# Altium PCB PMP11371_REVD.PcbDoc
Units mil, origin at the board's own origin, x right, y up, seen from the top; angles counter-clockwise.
Board outline 3400 x 2100 mil, 2 copper layers (Top Layer, Bottom Layer), stack 62 mil thick; 63 components, 36 nets, 176 pads, 55 vias.
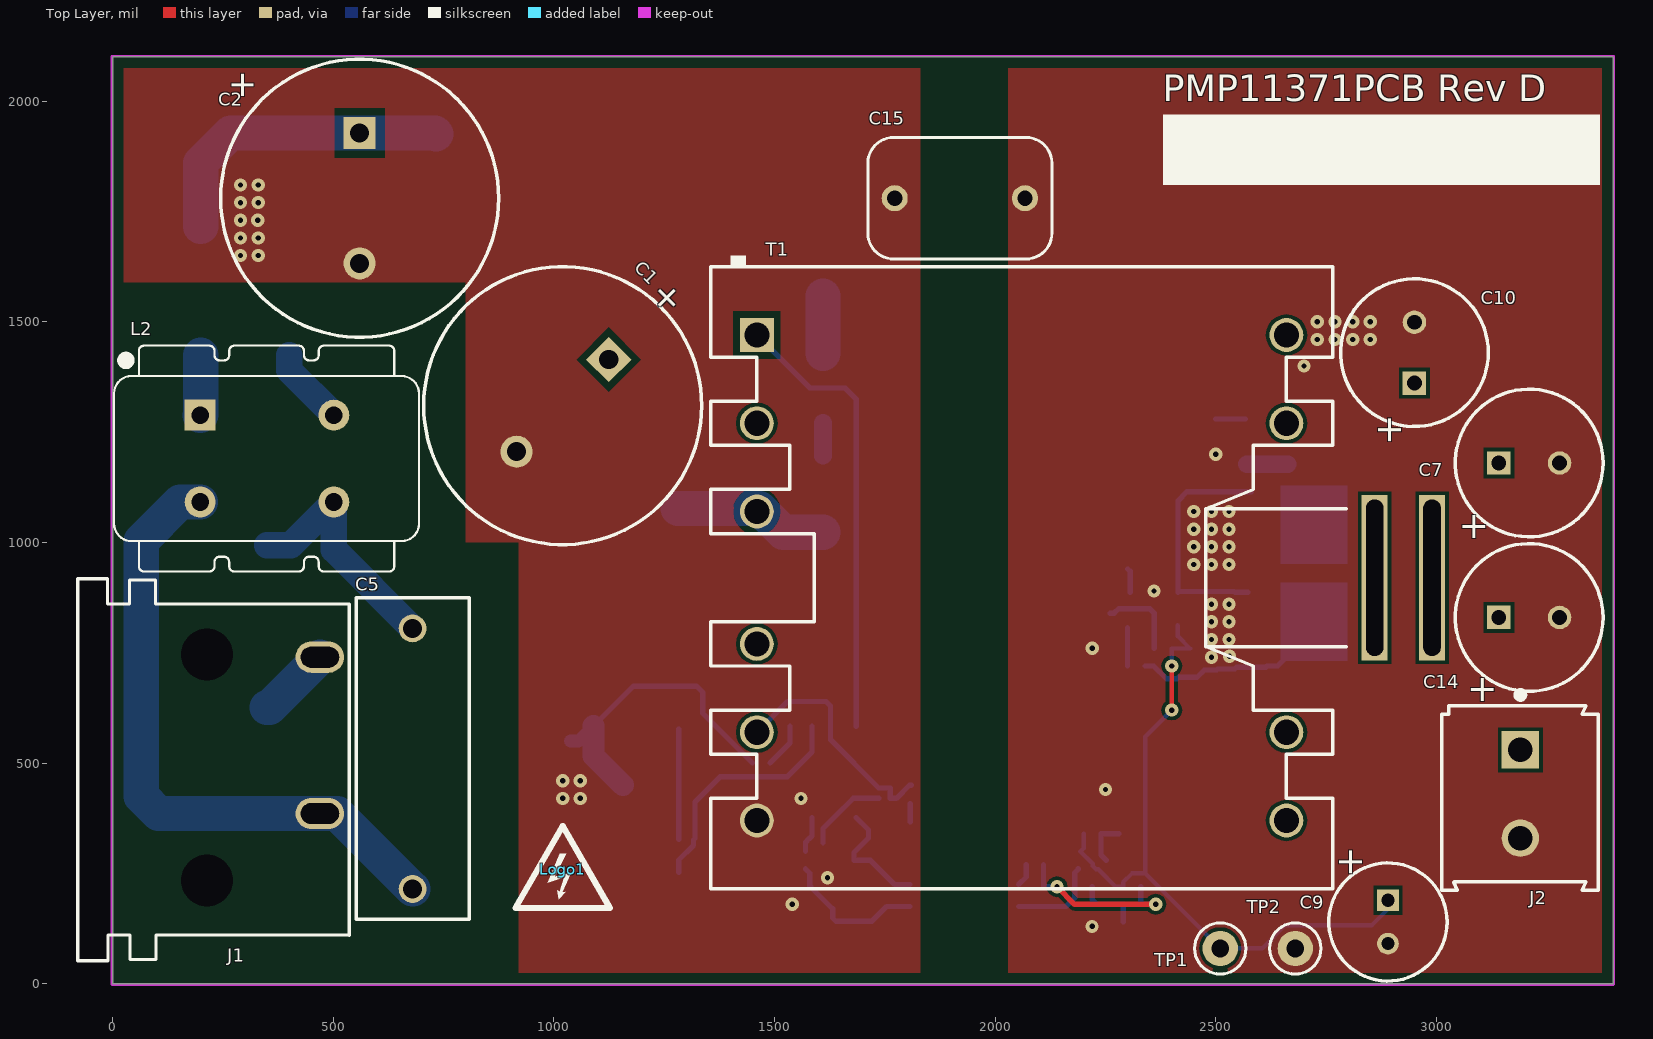
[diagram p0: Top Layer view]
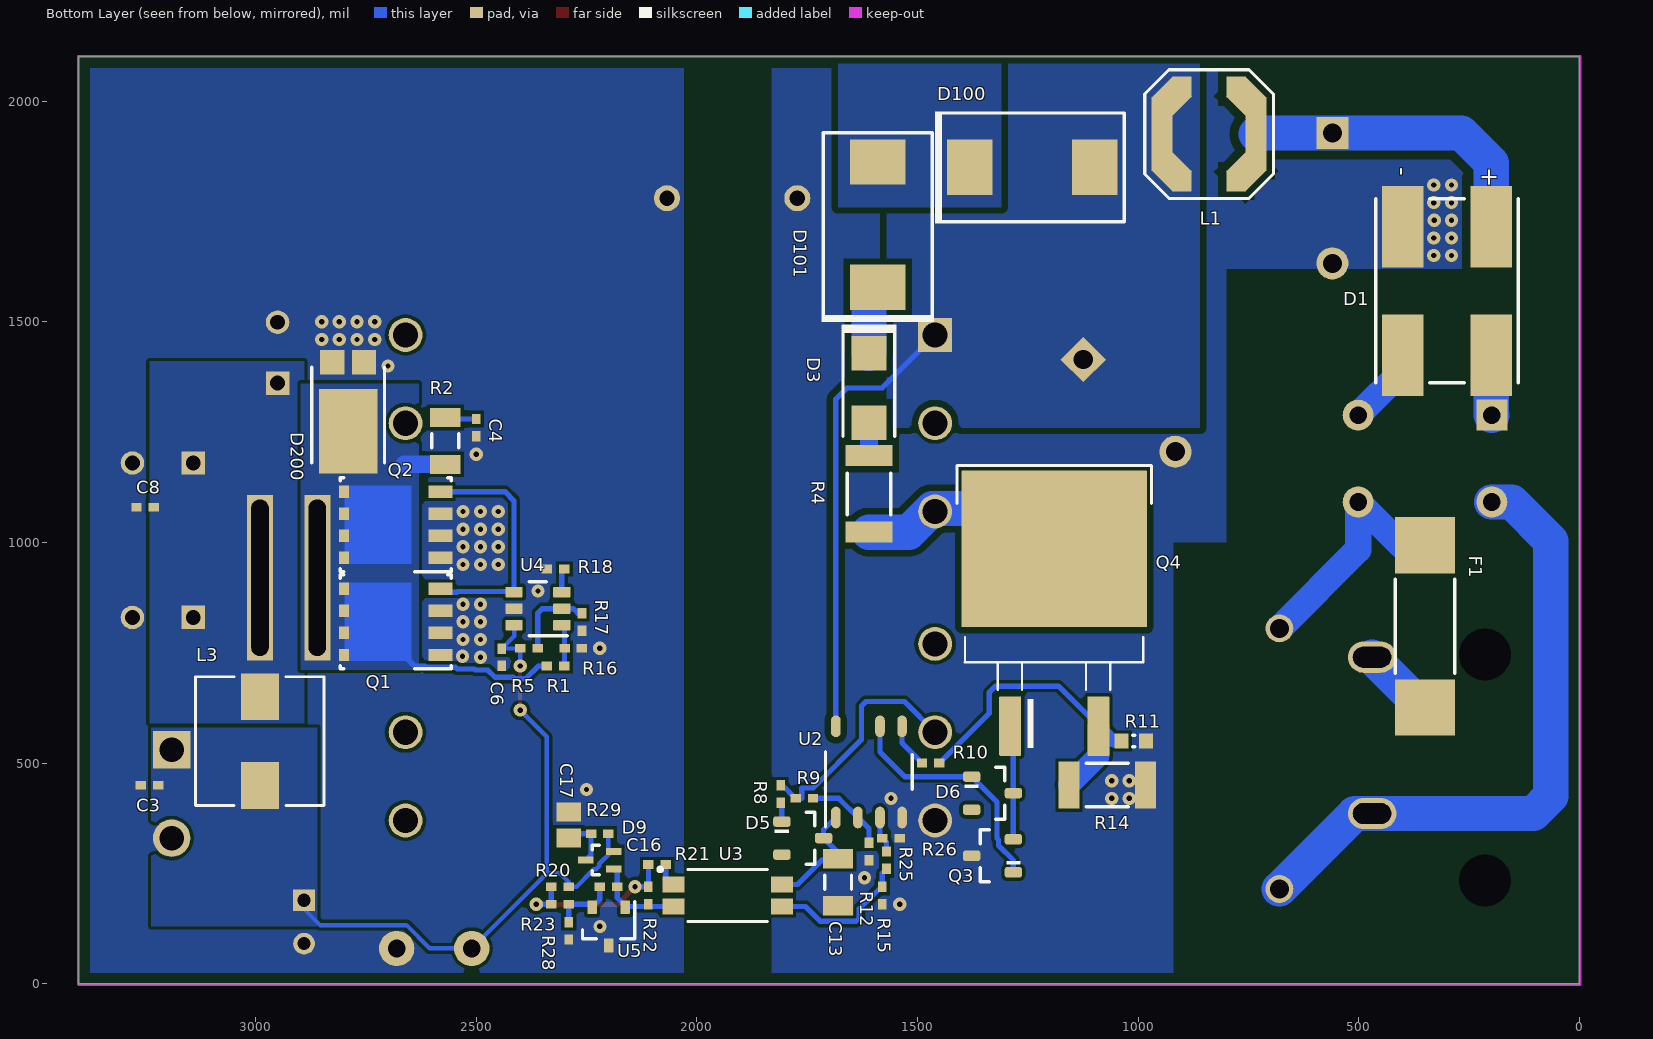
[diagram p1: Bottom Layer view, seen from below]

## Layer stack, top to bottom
Top Solder: solder mask 0.4, Solder Resist, Dk 3.5
Top Layer: signal copper 1.4
Dielectric1: core 59.2, FR-4, Dk 4.8
Bottom Layer: signal copper 1.4
Bottom Solder: solder mask 0.4, Solder Resist, Dk 3.5

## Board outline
0,0 3400,0 3400,2100 0,2100

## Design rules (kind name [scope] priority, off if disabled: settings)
AcuteAngle [All] p1: minimum=5.00000000000000E+0000 checktracksonly=FALSE
AssemblyTestPointUsage [All] p1: valid=2
Clearance "Schematic Clearance Constraint_5" [InNet('NetD3_1')] p1: gap=15
Clearance "Schematic Clearance Constraint_4" [InNet('NetD100_1')] p2: gap=15
Clearance "Schematic Clearance Constraint_3" [InNet('NetC2_1')] p3: gap=20
Clearance "Schematic Clearance Constraint_2" [InNet('NetQ4_4')] p4: gap=15
Clearance "Schematic Clearance Constraint_1" [InNet('NetC1_1')] p5: gap=15
Clearance "Schematic Clearance Constraint" [InNet('NetD3_2')] p6: gap=15
Clearance Clearance_Keepouts [((IsTrack Or IsArc) And Not InPoly) And IsFree and IsKeepOut vs ((IsTrack Or IsArc) And Not InPoly) And IsFree and IsKeepOut] p7: gap=0
Clearance Clearance_BoardEdge_MountingHoles [OnCopper and InComponentClass('Mounting Holes') vs IsKeepOut] p8: gap=40
Clearance Clearance_BoardEdge_Poly [OnCopper and InPoly vs IsKeepOut] p9: gap=25
Clearance Clearance_BoardEdge [OnCopper and Not InComponentClass('Logo') and not InComponentClass('FiducialMark') and not InRegion(1000,500,4000,800) and Not IsKeepout vs IsKeepOut] p10: gap=25
Clearance Clearance_Poly [InPolygon] p11: gap=8
Clearance [All] p12: gap=7.87
ComponentClearance ComponentClearance_MountingHoles_FiducialMarks [InComponentClass('Mounting Holes') vs InComponentClass('FiducialMark')] p1: gap=50 collisioncheckmode=3 verticalgap=10 showdistances=FALSE
ComponentClearance ComponentClearance_Shunt [InComponentClass('Header') vs InComponentClass('Shunt')] p2: gap=0 collisioncheckmode=3 verticalgap=0 showdistances=FALSE
ComponentClearance ComponentClearance_Logo [InComponentClass('Logo')] p3: gap=25 collisioncheckmode=3 verticalgap=10 showdistances=FALSE
ComponentClearance ComponentClearance_ScrewToNut [(HasFootprint('NY PMS 440 0025 PH')) vs (HasFootprint('Keystone_1902C'))] p4: gap=5 collisioncheckmode=3 verticalgap=10 showdistances=FALSE
ComponentClearance ComponentClearance_MountingHoles [InComponentClass('Mounting Holes')] p5: gap=25 collisioncheckmode=3 verticalgap=100000 showdistances=FALSE
ComponentClearance ComponentClearance_SmallPassives [HasFootprint('0201*') or HasFootprint('0402*') or HasFootprint('0508') or HasFootprint('0603*') or HasFootprint('0612') or HasFootprint('0805*') or HasFootprint('0815*') or HasFootprint('0830*') or HasFootprint('1206*') or HasFootprint('1210*') or HasFootprint('1808*') or HasFootprint('1812*') or HasFootprint('1825*') or HasFootprint('2010*') or HasFootprint('2220*') or HasFootprint('2225*') or HasFootprint('2512*') or HasFootprint('2728*') or HasFootprint('3518*') vs HasFootprint('0201*') or HasFootprint('0402*') or HasFootprint('0508') or HasFootprint('0603*') or HasFootprint('0612') or HasFootprint('0805*') or HasFootprint('0815*') or HasFootprint('0830*') or HasFootprint('1206*') or HasFootprint('1210*') or HasFootprint('1808*') or HasFootprint('1812*') or HasFootprint('1825*') or HasFootprint('2010*') or HasFootprint('2220*') or HasFootprint('2225*') or HasFootprint('2512*') or HasFootprint('2728*') or HasFootprint('3518*')] p6: gap=15 collisioncheckmode=3 verticalgap=10 showdistances=FALSE
ComponentClearance ComponentClearance_THtoSMT [IsThruComponent vs IsSMTComponent] p7: gap=15 collisioncheckmode=3 verticalgap=30 showdistances=FALSE
ComponentClearance ComponentClearance_THtoTH [IsThruComponent vs IsThruComponent] p8: gap=15 collisioncheckmode=3 verticalgap=30 showdistances=FALSE
ComponentClearance [All] p9: gap=15 collisioncheckmode=3 verticalgap=10 showdistances=FALSE
DiffPairsRouting [All] p1: maxlimit=100 minlimit=10 mostfreqgap=10 toplayer_minwidth=15 toplayer_maxwidth=15 toplayer_prefwidth=15 bottomlayer_minwidth=15 bottomlayer_maxwidth=15 bottomlayer_prefwidth=15 maxuncoupledlength=1000
FabricationTestPointUsage TestPointUsage [All] p1: valid=2 allowmultiple=FALSE
FabricationTestpoint Testpoint [All] p1: side=3 testpointundercomponent=TRUE minsize=40 maxsize=100 preferedsize=60 minholesize=0 maxholesize=40 preferedholesize=32 testpointgrid=1 allowsidetop=TRUE allowsidebottom=TRUE usegrid=TRUE gridtolerance=0.01
FanoutControl Fanout_LCC [IsLCC] p1: bgadir=Out bgaviamode=Centered fanoutstyle=Auto fanoutdirection=Alternating viagrid=1 // Fanout_LCC (Default Rule)
FanoutControl Fanout_BGA [IsBGA] p2: bgadir=Out bgaviamode=Centered fanoutstyle=Auto fanoutdirection=Alternating viagrid=1 // Fanout_BGA (Default Rule)
FanoutControl Fanout_Default [All] p4: bgadir=Out bgaviamode=Centered fanoutstyle=Auto fanoutdirection=Alternating viagrid=1 // Fanout_Default (Default Rule)
FanoutControl Fanout_Small [(CompPinCount < 5)] p5: bgadir=Out bgaviamode=Centered fanoutstyle=Auto fanoutdirection=OutThenIn viagrid=1 // Fanout_Small (Default Rule)
Height [All] p1: minheight=0 maxheight=1100 prefheight=500
HoleSize [All] p1: absolutevalues=TRUE maxlimit=251 minlimit=8 maxpercent=80.000 minpercent=20.000
MinimumAnnularRing MinimumAnnularRing_ThermalPadVias [IsVia and InAnyComponent] p1: minimumring=5.91
MinimumAnnularRing [All] p2: minimumring=9
MinimumSolderMaskSliver MinimumSolderMaskSliver_Logo [InComponentClass('Logo') vs InComponentClass('Logo')] p1: minsoldermaskwidth=0.7
MinimumSolderMaskSliver [All] p2: minsoldermaskwidth=1
PlaneConnect [All] p1: planeconnectstyle=Relief reliefexpansion=10 reliefentries=4 reliefconductorwidth=10 reliefairgap=10
PolygonConnect [All] p1: connectstyle=Direct reliefconductorwidth=10 reliefentries=4 polygonreliefangle="90 Angle" airgapwidth=10
RoutingVias ThermalPadVias [IsVia and InAnyComponent] p1: holewidth=7.87 width=19.68 viastyle="Through Hole" minholewidth=7.87 minwidth=19.68 maxholewidth=12.99 maxwidth=23.62
RoutingVias [All] p2: holewidth=16 width=34 viastyle="Through Hole" minholewidth=7.87 minwidth=26 maxholewidth=40 maxwidth=65
SilkToBoardRegionClearance [Not ((IsComment or IsDesignator) And (Hide <> 'False')) and not InRegion(1000,500,4000,800)] p1:
SilkToSilkClearance SilkToSilkClearance_Pb-FreeLogo [(HasFootprint('Pb-Free_Overlay_Medium') OR HasFootprint('Pb-Free_Overlay_Small')) vs (HasFootprint('Pb-Free_Overlay_Medium') OR HasFootprint('Pb-Free_Overlay_Small'))] p1: silktosilkclearance=0
SilkToSilkClearance [All] p2: silktosilkclearance=2
SilkToSolderMaskClearance SilkToComonentPadClearance [IsPad and InAnycomponent] p1: minsilkscreentomaskgap=0 clearancetoexposedcopper=TRUE
SilkToSolderMaskClearance "Silk to Solder Mask Opening" [All] p2: minsilkscreentomaskgap=0 clearancetoexposedcopper=FALSE
SolderMaskExpansion [All] p1: expansion=1.97
Width [All] p1: maxlimit=100 minlimit=6 preferedwidth=10 checkconnectedcopper=TRUE
14 further rules are at their usual default settings.

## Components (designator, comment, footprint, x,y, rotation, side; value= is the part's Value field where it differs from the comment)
C1 "EEUED2G470" CAPPR7.5-16X25 1020,1310 r225 top
C2 "EEUED2G330S" CAPPR7.5-16X20 560,1780 r270 top
C3 "GRM155R61A105KE15D" 0402L 3240,450 r0 bottom
C4 "GRM1555C1H470FA01D" 0402L 2500,1260 r90 bottom
C5 "890324025027CS" WCAP-FTX2_1800x600x1150 680,510 r270 top
C6 "GRM155R61A105KE15D" 0402L 2441.68,739.87 r270 bottom
C7 "16SEPC470M" CAPPRD350W60D800H800 3210,1180 r0 top
C8 "GRM155R61A105KE15D" 0402L 3250,1080 r0 bottom
C9 "EEU-EB1E101S" CAPPR250W50D630H1120 2890,140 r270 top
C10 "16SEPC470M" CAPPRD350W60D800H800 2950,1430 r90 top
C13 "GRM31CR71H475KA12L" 1206_180L 1680,230 r270 bottom
C14 "16SEPC470M" CAPPRD350W60D800H800 3210,830 r0 top
C15 "CS11-E2GA222MYNS" CAPRD750W60D1050H1450 1920,1780 r180 top
C16 "GRM155R71H223KA12D" 0402L 2200,220 r0 bottom
C17 "GRM219R61A106KE44D" 0805L 2290,360 r90 bottom
D1 "Z4DGP406L-HF" Z4-D 300,1570 r270 bottom
D3 "MURA160T3G" SMA 1610,1350 r270 bottom
D5 "BAS21-7-F" SOT-23 1760,330 r180 bottom
D6 "BAS16-7-F" SOT-23 1330,431.89 r180 bottom
D9 "BAT54ST-7-F" SOT-523 2220,280 r0 bottom
D100 "SMCJ70A" SMC_265 1240,1850 r180 bottom
D101 "SMCJ70A" SMC_265 1590,1720 r90 bottom
D200 "PDS1040L-13" PowerDI5 2790,1330 r270 bottom
F1 "0443003.DR" FUSE_0443 350,810 r270 bottom
J1 "770W-X2/10" CONN_AC_770W-SERIES 340,490 r90 top
J2 "282841-2" TEC_282841-2 3190,430 r270 top
L1 "LPS6235-333MLB" LPS6235 839.35,1925.43 r0 bottom
L2 "744822222" IND_WE-CMB-S 350,1190 r270 top
L3 "744314110" WE-HCI_7050 2990,550 r270 bottom
Logo1 "DANGER HIGH VOLTAGE" IEC_HighVoltage_Small 1020,260 r0 top
Q1 "CSD18540Q5B" TRANS_NexFET_Q5B 2690,820 r0 bottom
Q2 "CSD18540Q5B" TRANS_NexFET_Q5B 2690,1040 r0 bottom
Q3 "MMBT2907A" SOT-23 1330,290 r0 bottom
Q4 "AOB20S60L" DDPAK 1190,830 r90 bottom
R1 "CRCW0402249KFKED" 0402L 2320,720 r0 bottom
R2 "CRCW120651R0JNEA" 1206L 2570,1230 r270 bottom
R4 "CRCW20105R10JNEF" 2010L 1610,1110 r90 bottom
R5 "CRCW0402165KFKED" 0402L 2380,760 r0 bottom
R8 "CRCW040220R0FKED" 0402L 1810,430 r90 bottom
R9 "CRCW040280K6FKED" 0402L 1756.35,420 r0 bottom
R10 "CRCW04021K78FKED" 0402L 1470,500 r180 bottom
R11 "CRCW06032R00FKEA" 0603L 1010,550 r0 bottom
R12 "CRCW040224K9FKED" 0402L 1610,300 r90 bottom
R14 "CSRN2010FKR200" 2010L 1070,450 r0 bottom
R15 "CRCW040210K0FKED" 0402L 1580,200 r90 bottom
R16 "CRCW040210K0FKED" 0402L 2280,760 r0 bottom
R17 "CRCW040237K4FKED" 0402L 2260,820 r90 bottom
R18 "CRCW040220K0FKED" 0402L 2320,940 r180 bottom
R20 "CRCW04020000Z0ED" 0402L 2310,220 r0 bottom
R21 "CRCW04021K00FKED" 0402L 2090,270 r180 bottom
R22 "CRCW04024K99FKED" 0402L 2110,200 r90 bottom
R23 "CRCW040210K0FKED" 0402L 2310,180 r0 bottom
R25 "CRCW040249K9FKED" 0402L 1570,280 r90 bottom
R26 "CRCW040210K0FKED" 0402L 1560,330 r0 bottom
R28 "CRCW04028K25FKED" 0402L 2290,120 r90 bottom
R29 "CRCW0402100KFKED" 0402L 2220,340 r0 bottom
T1 "RLTI-1174" Renco_RLTI-1174 2060,920 r0 top
TP1 "5000" Keystone5000 2510,80 r0 top
TP2 "5001" Keystone5001 2680,80 r0 top
U2 "UCC28740DR" D0007A_L 1610,480 r90 bottom
U3 "VOS617A-7X001T" SSOP-4_VISHAY 1930,200 r180 bottom
U4 "UCC24636DBVR" DBV0006A_N 2360,850 r0 bottom
U5 "TL431AIDBZT" DBZ0003A_L 2200,130 r270 bottom

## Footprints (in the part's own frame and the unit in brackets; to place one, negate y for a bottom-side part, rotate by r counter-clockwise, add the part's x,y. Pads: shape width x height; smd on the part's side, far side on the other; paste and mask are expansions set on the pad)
0402L [mm] "0402 from SM-752 data"
  rect 0.6x0.5 smd: 1(-0.5,0) 2(0.5,0)
  body extent -0.55,-0.3 0.55,0.3, height 0.6
0603L [mm] "0603 from SM-752 data"
  rect 0.8x0.85 smd: 1(-0.7,0) 2(0.7,0)
  silkscreen extent -0.07,-0.33 0.07,0.33, body extent -0.87,-0.47 0.87,0.47, height 1
0805L [mm] "0805 from SM-752 data"
  rect 1.1x1.4 smd: 1(-0.75,0) 2(0.75,0)
  body extent -1.1,-0.72 1.1,0.72, height 1.45
1206_180L [mm] "1206_180"
  rect 1.1x1.75 smd: 1(-1.35,0) 2(1.35,0)
  silkscreen extent -0.4,-0.77 0.4,0.77, body extent -1.75,-0.95 1.75,0.95, height 1.8
1206L [mm] "1206 from SM-752 data"
  rect 1.1x1.75 smd: 1(-1.35,0) 2(1.35,0)
  silkscreen extent -0.4,-0.77 0.4,0.77, body extent -1.7,-0.9 1.7,0.9, height 1.35
2010L [mm]
  rect 1.2x2.7 smd: 1(-2.2,0) 2(2.2,0)
  silkscreen extent -1.2,-1.25 1.2,1.25, body extent -2.73,-1.45 2.73,1.45, height 1.66
CAPPR7.5-16X20 [mm] "Capacitor, Electrolytic, Radial; Body 16 x 20 mm (Dia.xH typ); Pin Spacing 7.5 mm (typ)"
  rect 1.85x1.85 hole 1.1: 1(-3.75,0)
  round 1.85 hole 1.1: 2(3.75,0)
  silkscreen extent -8,-8 8,8, body extent -8,-8.01 8,8.01, height 22
CAPPR7.5-16X25 [mm] "Capacitor, Electrolytic, Radial; Body 16 x 25 mm (Dia.xH typ); Pin Spacing 7.5 mm (typ)"
  rect 1.85x1.85 hole 1.1: 1(-3.75,0)
  round 1.85 hole 1.1: 2(3.75,0)
  silkscreen extent -8,-8 8,8, body extent -8,-8.01 8,8.01, height 27
CAPPR250W50D630H1120 [mm] "PANASONIC"
  rect 1.25x1.25 hole 0.75: 1(-1.25,0)
  round 1.25 hole 0.75: 2(1.25,0)
  silkscreen extent -3.4,-3.4 3.4,3.4, body extent -3.37,-3.39 3.4,3.39, height 12.21
CAPPRD350W60D800H800 [mm] "Based on Nichicon L8 series"
  rect 1.35x1.35 hole 0.85: 1(-1.75,0)
  round 1.35 hole 0.85: 2(1.75,0)
  silkscreen extent -4.25,-4.25 4.25,4.25, body extent -4.25,-4.24 4.25,4.24, height 9.01
CAPRD750W60D1050H1450 [mm] "TDK"
  round 1.5 hole 0.889: 1(-3.75,0) 2(3.75,0)
  silkscreen extent -5.3,-3.5 5.3,3.5, body extent -5.24,-3.5 5.24,3.5, height 14.46
CONN_AC_770W-SERIES [mm] "Qualtek Electronics"
  oval 1.8x2.8 hole 1.2 slot 2.2 at 90 deg: 1(6.35,-3.3) 2(-2.65,-3.3)
  round 2 hole 3 unplated: MH1(6.5,3.2) MH2(-6.5,3.2)
  silkscreen extent -11.12,-4.97 10.87,10.63, body extent -11.05,-4.8 10.8,10.6, height 22
D0007A_L [mm] "SOIC, 7-Leads, Body 4.9x3.9mm, Pitch 1.27mm, IPC High Density"
  oval 1.25x0.55 smd: 1(-2.625,1.905) 2(-2.625,0.635) 3(-2.625,-0.635) 4(-2.625,-1.905) 5(2.625,-1.905) 6(2.625,-0.635) 8(2.625,1.905)
  silkscreen extent -3.15,-2.5 1.17,2.5, body extent -3.01,-2.45 3.01,2.45, height 1.75
DBV0006A_N [mm] "SOT23, 6-Leads, Body 2.9x1.6mm, Pitch 0.95mm, Lead Span 2.8mm, IPC Medium Density"
  rrect17% 1x0.6 smd: 1(-1.375,0.95) 2(-1.375,0) 3(-1.375,-0.95) 4(1.375,-0.95) 5(1.375,0) 6(1.375,0.95)
  silkscreen extent -1.68,-1.55 0.5,1.55, body extent -1.42,-1.46 1.42,1.46, height 1.12
DBZ0003A_L [mm] "SOT23, 3-Leads, Body 2.9x1.3mm, Pitch 0.95mm, Lead Span 2.4mm, IPC High Density"
  rrect18% 0.8x0.55 smd: 1(-1.1,0.95) 2(-1.1,-0.95) 3(1.1,0)
  silkscreen extent -1.43,-1.5 0.7,1.5, body extent -1.26,-1.46 1.26,1.46, height 0.98
DDPAK [mil] "D2-PAK, 3-Pads, Body 9.7x10.4mm (max), TO-263AB, using Vishay Silionix recommended pad sizes"
  rrect8% 135x49.49 smd: 1(-246.06,100) 3(-246.06,-100)
  rrect1% 355x420 smd paste-181.1: 4(155.51,0)
  silkscreen extent -295,-220 344,220, body extent -295,-202 324,202, height 180
FUSE_0443 [mm] "LITTELFUSE"
  rect 3.25x3.43 smd: 1(-4.675,0) 2(4.675,0)
  silkscreen extent -2.7,-1.7 2.7,1.7, body extent -5.05,-1.56 5.05,1.56, height 3.12
IEC_HighVoltage_Small [mil]
  silkscreen extent -107,-88 107,97
IND_WE-CMB-S [mil] "Inductor, WE CMB Series Size S"
  rect 70x70 hole 40: 1(-98.43,-151.57)
  round 70 hole 40: 2(98.43,-151.57) 3(98.43,151.57) 4(-98.43,151.57)
  silkscreen extent -256,-346 256,344, body extent -256,-290 256,288, height 788
Keystone5000 [mil] "For Keystone 500x miniature loop terminals"
  round 80 hole 40: 1(0,0)
  silkscreen extent -58,-58 58,58, body extent -49,-49 49,49, height 182
Keystone5001 [mil] "For Keystone 500x miniature loop terminals"
  round 80 hole 40: 1(0,0)
  silkscreen extent -58,-58 58,58, body extent -49,-49 49,49, height 182
LPS6235 [mm] "Coilcraft recommended land pattern.  Document 587-2, rev 10/17/08"
  rect 1.2x4.25 smd: 1(-2.7,0) 2(2.7,0)
  rect 1.68x1.6 smd rot 135: 1(-2.126,-2.151) 2(2.126,2.151)
  rect 1.68x1.6 smd rot 45: 1(-2.126,2.151) 2(2.126,-2.151)
  rect 1.125x1.2 smd: 1(-1.562,-2.7) 1(-1.562,2.7) 2(1.562,-2.7) 2(1.562,2.7)
  silkscreen extent -3.7,-3.7 3.7,3.7, body extent -3.1,-3.1 3.1,3.1, height 3.52
PowerDI5 [mm] "Diodes Inc recommended land pattern, ap02001.pdf rev 60"
  rect 1.4x1.39 smd: 1(-1.991,0.92) 2(-1.991,-0.92)
  rect 4.86x3.36 smd: 3(1.991,0)
  silkscreen extent -1.7,-2.1 3.8,2.1, body extent -2.27,-2.02 4.33,2.03, height 1.17
Renco_RLTI-1174 [mm] "TH, 12-Leads, Body 1410x1410mil"
  rect 1.95x1.95 hole 1.45: 1(-15.24,13.97)
  round 1.95 hole 1.45: 2(-15.24,8.89) 3(-15.24,3.81) 4(-15.24,-3.81) 5(-15.24,-8.89) 6(-15.24,-13.97) 7(15.24,-13.97) 8(15.24,-8.89) 11(15.24,8.89) 12(15.24,13.97)
  rect 1.5x9.5 hole 1 slot 9 at 90 deg: A(20.32,0) B(23.622,0)
  silkscreen extent -17.91,-17.91 18.67,18.56, body extent -17.91,-17.91 24.26,17.91, height 24.13
SMA [mm] "Molded Diode, 2-Leads, Body 4.3x2.6mm, IPC Medium Density, based on OnSemi component dimensions and land pattern"
  rect 2x2 smd: 1(-2,0) 2(2,0)
  silkscreen extent -3.66,-1.57 2.79,1.57, body extent -2.6,-1.3 2.6,1.3, height 2.42
SMC_265 [mm] "SMD, 2-Leads, Body 7.15x6.25mm"
  rect 2.6x3.2 smd: 1(-3.6,0) 2(3.6,0)
  silkscreen extent -5.6,-3.22 5.3,3.23, body extent -4.08,-3.13 4.08,3.13, height 2.65
SOT-23 [mm] "SOT23, 3-Leads, Body 2.9x1.3mm, Pitch 0.95mm, Lead Span 2.5mm, IPC Medium Density"
  rrect50% 1x0.6 smd: 1(-1.2,0.95) 2(-1.2,-0.95) 3(1.2,0)
  silkscreen extent -1.63,-1.5 0.7,1.5, body extent -1.16,-1.45 1.21,1.45, height 1
SOT-523 [mm] "From Diodes Inc datasheet component parameters"
  rect 0.9x0.4 smd: 1(-0.8,0.5) 2(-0.8,-0.5) 3(0.8,0)
  silkscreen extent 0.02,-0.85 0.42,0.85, body extent -0.8,-0.8 0.8,0.8, height 0.79
SSOP-4_VISHAY [mm] "Vishay Recommened"
  rect 1.25x0.9 smd: 1(-3.125,0.635) 2(-3.125,-0.635) 3(3.125,-0.635) 4(3.125,0.635)
  silkscreen extent -3.98,-1.5 2.3,1.59, body extent -3.5,-1.45 3.5,1.45, height 2.42
TEC_282841-2 [mm] "TE Connectivity"
  rect 2.15x2.15 hole 1.4: 1(-2.54,0)
  round 2.15 hole 1.4: 2(2.54,0)
  silkscreen extent -5.9,-4.52 5.55,4.47, body extent -5.08,-4.52 5.58,4.48, height 15.2
TRANS_NexFET_Q5B [mm] "TI recommended land pattern (nominal) November 2012"
  rect 1.372x0.71 smd paste-0.4: 1(-2.776,1.905) 2(-2.776,0.635) 3(-2.776,-0.635) 4(-2.776,-1.905)
  rect 0.59x0.71 smd paste-0.3: 5(2.776,-1.905) 6(2.776,-0.635) 7(2.776,0.635) 8(2.776,1.905)
  Top Layer region: -1.106,2.26 2.744,2.26 2.744,-2.26 -1.106,-2.26
  silkscreen extent -3.38,-2.7 3,2.7, body extent -3.23,-2.55 2.87,2.55, height 1.06
WCAP-FTX2_1800x600x1150 [mm] "TH, 2-Leads, Body 18x6mm, Lead Spacing 15mm"
  round 1.6 hole 1.1: 1(-7.5,0) 2(7.5,0)
  silkscreen extent -9.25,-3.25 9.25,3.25, body extent -9.25,-3.25 9.25,3.25, height 12
WE-HCI_7050 [mm] "Wurth Electronik recommended land pattern"
  rect 2.7x2.2 smd: 1(-2.55,0) 2(2.55,0)
  silkscreen extent -3.7,-3.7 3.7,3.7, body extent -3.6,-3.6 3.6,3.6, height 5
Z4-D [mm] "SMD, 4-Leads, Body 8.1x10.5mm"
  rect 4.7x2.4 smd: 1(-3.7,2.55) 2(3.7,2.55) 3(3.7,-2.55) 4(-3.7,-2.55)
  silkscreen extent -5.3,-4.1 5.3,4.1, body extent -5.3,-4.1 5.3,4.1, height 1.56

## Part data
C1: "CAP, AL, 47 µF, 400 V, +/- 20%, 0.609529 ohm, TH"
C2: "CAP, AL, 33 µF, 400 V, +/- 20%, 0.868117 ohm, TH"
C3 C6 C8: "CAP, CERM, 1uF, 10V, +/-10%, X5R, 0402"
C4: "CAP, CERM, 47 pF, 50 V, +/- 1%, C0G/NP0, 0402"
C5: "CAP, Film, 0.22 µF, 275 V, +/- 10%, TH"
C7 C10 C14: library part RL80J821MDN1KX, "CAP POLYMER 470UF 20% 16V T/H"
C9: "CAP, AL, 100 µF, 25 V, +/- 20%, TH"
C13: "CAP, CERM, 4.7 µF, 50 V, +/- 10%, X7R, 1206"
C15: "CAP, CERM, 2200 pF, 250 V, +/- 20%, E, Radial Disc D10.5x7mm"
C16: "CAP, CERM, 0.022 µF, 50 V, +/- 10%, X7R, 0402"
C17: "CAP, CERM, 10 µF, 10 V, +/- 10%, X5R, 0805"
D1: "Diode, P-N-Bridge, 600 V, 4 A, Z4-D"
D3: "Diode, Ultrafast, 600 V, 1 A, AEC-Q101, SMA"
D5: "Diode, Switching, 200 V, 0.2 A, SOT-23"
D6: "Diode, Ultrafast, 75 V, 0.3 A, SOT-23"
D9: "Diode, Schottky, 30 V, 0.2 A, SOT-523"
D100 D101: "Diode, TVS, Uni, 70 V, 1500 W, SMC"
D200: "Diode, Schottky, 40 V, 10 A, PowerDI5"
F1: "Fuse, 3 A, 250 V, SMD"
J1: "AC Receptacle, 2.5A, R/A, TH"
J2: "Terminal Block, 2x1, 5.08mm, TH"
L1: "Inductor, Shielded Drum Core, Ferrite, 33 µH, 1.3 A, 0.18 ohm, SMD"
L2: library part 744822301, "COMMON MODE CHOKE 2A 2 LN T/H"
L3: "Inductor, Shielded Drum Core, Superflux, 1.1 µH, 13 A, 0.0032 ohm, SMD"
Logo1: library part IEC_HighVoltage, "IEC 61010-1 High Voltage Warning"
Q1 Q2: "MOSFET, N-CH, 60 V, 28 A, SON 5x6mm"
Q3: library part "MMBT2907A, Fairchild Semiconductor", "Transistor, PNP, 60 V, 0.8 A, SOT-23"
Q4: "MOSFET, N-CH, 600 V, 20 A, DDPAK"
R1: "RES, 249 k, 1%, 0.063 W, 0402"
R2: "RES, 51, 5%, 0.25 W, 1206"
R4: "RES, 5.1, 5%, 0.75 W, AEC-Q200 Grade 0, 2010"
R5: "RES, 165 k, 1%, 0.063 W, 0402"
R8: "RES, 20.0, 1%, 0.063 W, 0402"
R9: "RES, 80.6 k, 1%, 0.063 W, 0402"
R10: "RES, 1.78 k, 1%, 0.063 W, 0402"
R11: "RES, 2.00, 1%, 0.1 W, 0603"
R12: "RES, 24.9 k, 1%, 0.063 W, 0402"
R14: "RES, 0.2, 1%, 1 W, 2010"
R15 R16 R23 R26: "RES, 10.0 k, 1%, 0.063 W, 0402"
R17: "RES, 37.4 k, 1%, 0.063 W, 0402"
R18: "RES, 20.0 k, 1%, 0.063 W, 0402"
R20: "RES, 0, 5%, 0.063 W, 0402"
R21: "RES, 1.00 k, 1%, 0.063 W, 0402"
R22: "RES, 4.99 k, 1%, 0.063 W, 0402"
R25: "RES, 49.9 k, 1%, 0.063 W, 0402"
R28: "RES, 8.25 k, 1%, 0.063 W, 0402"
R29: "RES, 100 k, 1%, 0.063 W, 0402"
T1: "Flyback Transformer, 100uH, TH"
TP1: "Test Point, Miniature, Red, TH"
TP2: "Test Point, Miniature, Black, TH"
U2: "Constant-Voltage, Constant-Current Flyback Controller Using Opto-Coupler Feedback, D0007A"
U3: "OptoCoupler, Phototransitor, 80-160%, SSOP-4"
U4: "SYNCRONOUS RECTIFIER CONTROLLER WITH LOW POWER STANDBY, DBV0006A"
U5: "Adjustable Precision Shunt Regulator, 34 ppm / degC, 100 mA, -40 to 85 degC, 3-pin SOT-23 (DBZ), Green (RoHS & no Sb/Br)"

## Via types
v1: diameter 30, hole 12, Top Layer to Bottom Layer, 55 vias

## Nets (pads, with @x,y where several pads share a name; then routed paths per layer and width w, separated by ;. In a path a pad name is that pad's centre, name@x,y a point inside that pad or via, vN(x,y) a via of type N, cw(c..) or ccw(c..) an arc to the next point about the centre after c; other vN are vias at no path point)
GND: C3.2 C4.1 C6.2 C7.2 C8.2 C9.2 C10.2 C14.2 C15.1 C17.2 D200.1 D200.2 J2.2 Q1.1 Q1.2 Q1.3 Q2.1 Q2.2 Q2.3 R16.1 R17.1 R18.1 R28.1 TP2.1 U4.5 U5.3
  other v1: 2219.68,130 2250,440 2490,740 2530.98,742 2220,760 2490,780 2530,780 2490,820 2530,820 2490,860 2530,860 2360,890 2450,950 2490,950 2530,950 2450,990 2490,990 2530,990 2450,1030 2490,1030 2530,1030 2450,1070 2490,1070 2530,1070 2500,1200 2700,1400 2730,1460 2770,1460 2810,1460 2850,1460 2730,1500 2770,1500 2810,1500 2850,1500
NetC1_1: C1.1 D100.2 L1.2 T1.1 U2.8 | length 1026.7
  Bottom Layer w12: T1.1 1580,1350 1660,1350 1685,1325 U2.8
NetC2_1: C2.1 D1.1 L1.1 | length 706.5
  Bottom Layer w80: D1.1 199.61,1859.61 267.64,1927.64 C2.1 730.85,1927.64 L1.1@733.05,1925.43
NetC4_2: C4.2 R2.1 | length 66.5
  Bottom Layer w12: C4.2 R2.1@2566.54,1279.69
NetC5_1: C5.1 F1.1 L2.3 | length 552.2
  Bottom Layer w60: F1.1 404.06,994.06 L2.3 501.57,983.7 C5.1
NetC5_2: C5.2 J1.2 L2.2 | length 1450.4
  Bottom Layer w80: L2.2 153.31,1091.57 65,1003.27 65,425 104.33,385.67 J1.2 509.06,385.67 C5.2
NetC7_1: C7.1 C8.1 C10.1 C14.1 L3.1 T1.B
NetC16_1: C16.1 D9.1 R22.1 U3.2 U5.1 | length 204.6
  Bottom Layer w12: U3.2 2160.91,175 2180.32,194.41 C16.1 2180.32,252.13 D9.1
NetC16_2: C16.2 R23.1 R28.2 U5.2 | length 144.2
  Bottom Layer w12: C16.2 2219.69,191.02 2230.71,180 R23.1 R28.2@2290.32,140
NetC17_1: C17.1 D9.3 R29.2 | length 105.7
  Bottom Layer w12: D9.3 2239.69,291.81 R29.2 C17.1@2280.47,340
NetD1_2: D1.2 L2.1 | length 136.4
  Bottom Layer w80: L2.1 199.61,1289.61 D1.2
NetD1_3: D1.3 L2.4 | length 177.8
  Bottom Layer w60: D1.3 400.39,1389.61 L2.4
NetD3_1: D3.1 D101.1 | length 129.5
  Bottom Layer w80: D3.1 D101.1@1610,1558.27
NetD3_2: D3.2 R4.2 | length 74.6
  Bottom Layer w40: R4.2 D3.2
NetD5_1: D5.1 R8.1 | length 40.2
  Bottom Layer w12: D5.1 R8.1@1807.24,407.56
NetD6_1: D6.1 Q3.1 U2.6 | length 545
  Bottom Layer w12: Q3.1 1282.76,279.74 1316.32,313.3 1316.32,326.32 1320,330 1320,412.05 D6.1 1529.29,469.29 1585,525 U2.6
NetD6_3: D6.3 Q3.2 Q4.1 | length 249.3
  Bottom Layer w12: Q3.2 D6.3 Q4.1@1282.76,576.69
NetD100_1: D100.1 D101.2
NetD200_3: D200.3 Q1.5 Q1.6 Q1.7 Q1.8 Q2.5 Q2.6 Q2.7 Q2.8 R1.2 R2.2 T1.A | length 459.8
  Bottom Layer w12: R1.2 2359.17,720 2388.04,691.13 2411.96,691.13 2415.34,694.5 2457.27,694.5 2473.89,711.13 2501.96,711.13 2503.96,713.13 2542.94,713.13 2546.97,717.15 2613.45,717.15 2616.3,720 2640,720 2670,750
  Bottom Layer w40: R2.2 2663.15,1176.85
NetF1_2: F1.2 J1.1 | length 167.2
  Bottom Layer w80: F1.2 355.87,625.94 J1.1
NetQ1_4: Q1.4 Q2.4 U4.4 | length 541.5
  Bottom Layer w12: U4.4 U4.4@2414.13,888.87 ; Q1.4@2573.1,887.4 2543.43,887.4 2541.96,888.87 U4.4@2414.13,888.87 ; Q2.4 2435,1115 2414.13,1094.13 U4.4@2414.13,888.87
NetQ4_3: Q4.3 R10.2 R11.2 R14.2 | length 725.5
  Bottom Layer w12: Q4.3 1180.37,674.31 1323.06,674.31 1337.62,659.75 1337.62,612.7 R10.2
  Bottom Layer w30: R11.2 1056.06,550 Q4.3
  Bottom Layer w50: Q4.3 1090,516.61 R14.2
NetQ4_4: Q4.4 R4.1 T1.3 | length 350.8
  Bottom Layer w80: Q4.4@1281.34,1076.85 1466.06,1076.85 1519.53,1023.39 R4.1
NetR1_1: R1.1 R16.2 U4.1 | length 85.8
  Bottom Layer w12: R1.1@2299.69,720.63 R16.2 U4.1@2299.69,806.42
NetR5_1: R5.1 R17.2 U4.2 | length 188.5
  Bottom Layer w12: R17.2 2269.69,839.69 2280,850 U4.2 2350,850 2360.32,839.68 R5.1
NetR8_2: R8.2 R9.2 T1.5 | length 540.6
  Bottom Layer w12: T1.5 1529.46,639.46 1616.84,639.46 1626.93,629.37 1626.93,553.07 1736.28,443.72 1762.35,443.72 1762.35,420 R9.2 1805.73,449.69 R8.2
NetR9_1: R9.1 R12.2 U2.2 | length 186.9
  Bottom Layer w12: R12.2 1610,351.65 U2.2 1678.35,420 R9.1
NetR10_1: R10.1 U2.5 | length 102.1
  Bottom Layer w12: R10.1 1535,545.32 U2.5
NetR15_2: R15.2 R25.1 U3.3 | length 330.1
  Bottom Layer w12: R25.1 1580,250.32 R15.2 1581.9,219.69 1631.68,169.91 1631.68,149.45 1639.8,141.32 1720.2,141.32 1753.87,175 U3.3
NetR18_2: R18.2 U4.3 | length 54.9
  Bottom Layer w12: R18.2 2305.87,934.45 U4.3
NetR20_2: R20.2 R21.1 R22.2 R23.2 | length 394
  Top Layer w12: v1(2140,220) 2180,180 v1(2363.7,180)
  Bottom Layer w12: R22.2@2109.68,220 R21.1 ; R22.2 v1@2139.69,219.69 ; R20.2 R23.2 v1(2363.7,180)
NetR21_2: R21.2 U3.1 | length 52.2
  Bottom Layer w12: U3.1 2070.31,242.28 R21.2
NetR25_2: R25.2 R26.2 U2.3 | length 83.4
  Bottom Layer w12: R25.2 1570,320.31 R26.2 ; R26.2@1580,329.69 1585,334.69 U2.3
PGND: C1.2 C2.2 C13.2 C15.2 D1.4 Q3.3 R11.1 R12.1 R14.1 R15.1 R26.1 T1.6 U2.4
  other v1: 1540,180 1620,240 1020,420 1060,420 1560,420 1020,460 1060,460 290,1650 330,1650 290,1690 330,1690 290,1730 329.2,1729.79 290,1770 330,1770 290,1810 330,1810
VDD: C13.1 D5.3 U2.1 U3.4 | length 271.7
  Bottom Layer w12: U2.1 1712.76,348.9 D5.3 1680,297.24 1680,279.61 1717.22,279.61 1771.83,225 U3.4
VOUT: C3.1 C6.1 C9.1 D9.2 J2.1 L3.2 R5.2 R20.1 R29.1 TP1.1 U4.6 | length 1542.5
  Top Layer w10: v1(2400,620) v1(2400,720)
  Bottom Layer w10: R29.1 2200.32,307.07 2192.93,299.69 2220.91,271.71 2220.91,266.79 2228.45,259.25 2233.36,259.25 2272.62,220 R20.1 2290.32,230.39 2310,250.08 2339.92,250.08 ; v1(2400,620) 2339.92,559.92 2339.92,250.08 ; v1@2400.13,720.13 2400.13,759.56 C6.1 2414.13,787.11 U4.6 ; C9.1@2890,169.21 2853.66,132.87 2658.1,132.87 2605.22,80 TP1.1 2339.92,250.08
pads on no net: D5.2 D6.2 J1.MH1 J1.MH2 T1.2 T1.4 T1.7 T1.8 T1.11 T1.12

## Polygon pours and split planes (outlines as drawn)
NetC1_1 on Bottom Layer "Bottom Layer-VDC" (solid, remove dead copper, pour order 39): 860,2100 860,1260 1570,1260 1570,2100
PGND on Bottom Layer "Bottom Layer-PGND" (solid, remove dead copper, pour order 42): 210,2100 210,1620 1830,1620 1830,2100
PGND on Bottom Layer "Bottom Layer-PGND" (solid, remove dead copper, pour order 44): 800,1970 800,1000 1830,1000 1830,1970
PGND on Bottom Layer "Bottom Layer-PGND" (solid, remove dead copper, pour order 46): 920,1070 920,0 1830,0 1830,1070
GND on Bottom Layer "Bottom Layer-GND" (solid, remove dead copper, pour order 48): 2030,2100 2030,0 3400,0 3400,2100
NetD200_3 on Bottom Layer "NETD200_3_L02_P035" (solid, remove dead copper, pour order 35): 2630,1360 2630,711.54 2897.53,711.54 2897.53,1360
NetC7_1 on Bottom Layer "NETC7_1_L02_P036" (solid, remove dead copper, pour order 36): 2890,1410 2890,590 3240,590 3240,1410
VOUT on Bottom Layer "VOUT_L02_P037" (solid, remove dead copper, pour order 37): 2860,580 2860,130 3235.67,130 3235.67,580
NetD100_1 on Bottom Layer "NETD100_1_L02_P038" (solid, remove dead copper, pour order 38): 1310,2100 1310,1760 1680,1760 1680,2100
PGND on Top Layer "Top Layer-PGND" (solid, remove dead copper, pour order 27): 10,2100 10,1590 1830,1590 1830,2100
PGND on Top Layer "Top Layer-PGND" (solid, remove dead copper, pour order 33): 800,1640 800,1000 1830,1000 1830,1640
PGND on Top Layer "Top Layer-PGND" (solid, remove dead copper, pour order 34): 920,1090 920,0 1830,0 1830,1090
GND on Top Layer "Top Layer-GND" (solid, remove dead copper, pour order 50): 2030,2110.03 2030,-10.03 3400,-10.03 3400,2110.03

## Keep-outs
Keep-Out Layer:
  lines w5: -2.5,0 ccw(c0,0) 0,-2.5 ; -2.5,0 ccw(c0,0) 0,-2.5 ; -2.5,0 -2.5,2100 ; -2.5,2100 cw(c0,2100) 0,2102.5 ; -2.5,2100 cw(c0,2100) 0,2102.5 ; 0,-2.5 3400,-2.5 ; 0,2102.5 3400,2102.5 ; 3400,-2.5 ccw(c3400,0) 3402.5,0 ; 3400,-2.5 ccw(c3400,0) 3402.5,0 ; 3400,2102.5 cw(c3400,2100) 3402.5,2100 ; 3400,2102.5 cw(c3400,2100) 3402.5,2100 ; 3402.5,0 3402.5,2100
  text ".Layer_Name" at 577,-858.49 h60

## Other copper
Top Layer:
  text ".Layer_Name" at 577,-858.49 h60
Bottom Layer:
  text ".Layer_Name" at 577,-858.49 h60

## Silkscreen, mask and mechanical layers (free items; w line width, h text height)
Top Overlay:
  rectangle: 2380,1810 3370,1970
  text "PMP11371PCB Rev D" at 2380,2000 h60
  text ".Layer_Name" at 577,-858.49 h60
Bottom Overlay:
  text ".Layer_Name" at 577,-858.49 h60
Top Paste:
  text ".Layer_Name" at 577,-858.49 h60
Bottom Paste:
  text ".Layer_Name" at 577,-858.49 h60
Top Solder:
  text ".Layer_Name" at 577,-858.49 h60
  text ".Layer_Name" at 577,-858.49 h60
Bottom Solder:
  text ".Layer_Name" at 577,-858.49 h60
Drill Guide:
  text ".Layer_Name" at 577,-858.49 h60
M1 Board Outline:
  the board outline again, w5
  text ".Layer_Name" at 577,-858.49 h60
M2 Board Dimensions:
  rectangle: 125,-400 500,-275
  rectangle: 0,-275 125,-150
  lines w7: 0,-275 1000,-275 ; 125,-400 125,-150 ; 250,-400 250,-150 ; 500,-400 500,-150 ; 750,-400 750,-150 ; 0,-400 0,-150 1000,-150 1000,-400 0,-400
  text ".Layer_Name" at 577,-858.49 h60
M3 3D STEP Top:
  text ".Layer_Name" at 577,-858.49 h60
M4 3D STEP Bottom:
  text ".Layer_Name" at 577,-858.49 h60
M5 Assembly Top:
  lines w10: -292,-930.17 6308,-930.17 ; -292,-726.83 6310,-726.83 ; -292,-523.5 -292,-1133.5 3713,-1133.5 6310,-1133.5 6310,-523.5 -291.5,-523.5 -291.5,-1133.5 1284,-1133.5 ; 2173,-1133.5 2173,-523.5 ; 3440,-726.83 3440,-523.5 ; 4280,-726.83 4280,-523.5 ; 4902,-1140 4902,-937.17
  text "COMPONENTS MARKED 'DNP' SHOULD NOT BE POPULATED." at 1153.5,-318.5 h60
  text "ASSEMBLY VARIANT:" at 1153,-434 h60
  text ".VariantName" at 2189,-434 h60
  text "PCB VIEWED FROM TOP SIDE" at -228.5,-655.67 h60
  text "BOARD #:" at 2248,-655.67 h60
  text ".PRJ_Number" at 2793.5,-655.67 h60
  text "REV:" at 3638,-655.67 h60
  text ".PCB_Rev" at 3929.5,-655.67 h60
  text "SVN REV:" at 4476,-655.67 h60
  text ".VersionControl_RevNumber" at 4982,-655.67 h60
  text "TID #:" at 2248,-859 h60
  text ".TID" at 2793.5,-859 h60
  text "PLOT NAME =" at -228.5,-1064.34 h60
  text ".plot_File_Name" at 577,-1064.34 h60
  text "GENERATED    :" at 2250,-1064.34 h60
  text ".Print_Date" at 3119.5,-1064.34 h60
  text ".Print_Time" at 3848.5,-1064.34 h60
  text "TEXAS INSTRUMENTS" at 5113,-1064.34 h60
M6 Assembly Bottom:
  lines w10: -292.5,-727.33 6309.5,-727.33 ; -290.5,-930.67 6309.5,-930.67 ; 1115.5,-1140.5 1115.5,-937.67 ; 1737.5,-727.33 1737.5,-524 ; 2577.5,-727.33 2577.5,-524 ; 3844.5,-1134 3844.5,-524 ; 4733.5,-1134 6309,-1134 6309,-524 -292.5,-524 -292.5,-1134 2304.5,-1134 6309.5,-1134 6309.5,-524
  text "COMPONENTS MARKED 'DNP' SHOULD NOT BE POPULATED." at 6102,-318 h60
  text ".VariantName" at 5058,-434 h60
  text "ASSEMBLY VARIANT:" at 6097,-434 h60
  text ".VersionControl_RevNumber" at 1035.5,-656.17 h60
  text "SVN REV:" at 1541.5,-656.17 h60
  text ".PCB_Rev" at 2088,-656.17 h60
  text "REV:" at 2379.5,-656.17 h60
  text ".PRJ_Number" at 3224,-656.17 h60
  text "BOARD #:" at 3769.5,-656.17 h60
  text "PCB VIEWED FROM BOTTOM SIDE" at 6246,-656.17 h60
  text ".TID" at 3224,-859.5 h60
  text "TID #:" at 3769.5,-859.5 h60
  text "TEXAS INSTRUMENTS" at 904.5,-1064.84 h60
  text ".Print_Time" at 2169,-1064.84 h60
  text ".Print_Date" at 2898,-1064.84 h60
  text "GENERATED    :" at 3767.5,-1064.84 h60
  text ".plot_File_Name" at 5440.5,-1064.84 h60
  text "PLOT NAME =" at 6246,-1064.84 h60
M9 Title Sheet:
  drawing of 57 lines, arcs and shapes, not listed
  text "1" at 739.84,8036.5 h70
  text "2" at 3235.5,8036.5 h70
  text "3" at 5724.84,8036.5 h70
  text "4" at 8231.51,8036.5 h70
  text "5" at 10730.5,8036.5 h70
  text "6" at 13235.5,8036.5 h70
  text "A" at -416.5,6893.5 h70
  text "A" at 14383.5,6893.5 h70
  text "B" at -416.5,4513.5 h70
  text "B" at 14383.5,4513.5 h70
  text "C" at -416.5,2138.5 h70
  text "C" at 14383.5,2138.5 h70
  text "PROJECT TITLE:" at 11343.5,277.5 h45
  text ".PRJ_Title" at 11393.5,144.17 h70
  text "DESIGNED FOR:" at 11343.5,-23.5 h45
  text ".PRJ_Customer" at 11393.5,-163.5 h70
  text "D" at -416.5,-231.5 h70
  text "D" at 14383.5,-231.5 h70
  text "FILE NAME:" at 11343.5,-323.5 h45
  text ".PCB_File_Name_No_Path" at 11393.5,-443.5 h70
  text "Texas Instruments (TI) and/or its licensors do not warrant the accuracy or completeness of this specification" at 6374,-605.34 h45
  text "ENGINEER:" at 11343.5,-613.5 h45
  text "LAYOUT BY:" at 12848.5,-613.5 h45
  text "or any information contained therein. TI and/or its licensors do not warrant that this design will meet" at 6329.01,-718 h45
  text ".PRJ_Engineer" at 11393.5,-768.49 h70
  text ".PCB_Layout" at 12899,-768.49 h70
  text "the specifications, will be suitable for your application or fit for any particular purpose, or will operate in" at 6329.01,-830.67 h45
  text ".Layer_Name" at 577,-858.49 h60
  text "ALTIUM DESIGNER VERSION:" at 12848.5,-923.5 h45
  text "an implementation. TI and/or its licensors do not warrant that the design is production worthy. You should" at 6329.01,-943.33 h45
  text "completely validate and test your design implementation to confirm the system functionality for your application." at 6374,-1056 h45
  text ".print_Scale" at 11393.5,-1056.83 h70
  text ".Application_BuildNumber" at 12899,-1056.83 h70
  text "1" at 739.84,-1263.5 h70
  text "2" at 3235.5,-1263.5 h70
  text "3" at 5724.84,-1263.5 h70
  text "4" at 8231.51,-1263.5 h70
  text "5" at 10730.5,-1263.5 h70
  text "6" at 13235.5,-1263.5 h70
M10 Fab Notes:
  drawing of 189 lines, arcs and shapes, not listed
  text "DESIGN INFORMATION" at 12381.02,6028 h60
  text "MIN. TRACK WIDTH:" at 11736.46,5848 h60
  text "8" at 12832.7,5848 h60
  text "MIL" at 12987.46,5848 h60
  text "MIN. CLEARANCE:" at 11736.46,5716 h60
  text "0.2" at 12772.7,5716 h60
  text "mm" at 12987.46,5716 h60
  text "MIN. VIA PAD SIZE:" at 11736.46,5584 h60
  text "24" at 12802.71,5584 h60
  text "MIL" at 12987.46,5584 h60
  text "0.05mm (2MIL)" at 12431.46,5442.29 h60
  text "MINIMUM ANNULAR RING" at 11407.23,5438 h60
  text "EXTERNAL" at 13139.46,5438 h60
  text "PER" at 11607.23,5320 h60
  text "IPC-D-275 CLASS 2 LEVEL C" at 11827.23,5320 h60
  text "MIL, HOLES" at 13315.46,5207.71 h60
  text "+/-" at 12923,5207 h60
  text "+/-" at 13777,5207 h60
  text "REGISTRATION TOLERANCES:" at 11407.23,5202 h60
  text "METAL" at 12607,5202 h60
  text "5" at 13183.2,5202 h60
  text "3" at 14016.2,5202 h60
  text "MIL" at 14132.46,5202 h60
  text "+/-" at 13777,5089 h60
  text "HOLE SIZE TOLERANCE (UNLESS OTHERWISE SPECIFIED):" at 11407.23,5084 h60
  text "3" at 14016.2,5084 h60
  text "MIL" at 14132.46,5084 h60
  text "MATERIAL:" at 11332.46,4874.54 h60
  text "FR-4 High Tg" at 12318.9,4734.21 h60
  text "FR-408" at 11753.46,4725.64 h60
  text "OTHER" at 13241.46,4725.64 h60
  text "X" at 12164,4722 h60
  text "62 MIL (1.6mm) +/-10%" at 12073.56,4562.92 h60
  text "THICKNESS:" at 11407.23,4558.64 h60
  text "X" at 11945.4,4558.64 h60
  text "OTHER" at 13358.46,4558.64 h60
  text "TOLERANCE:" at 11407.23,4400.64 h60
  text "X" at 12246.53,4400.64 h60
  text "ANSI IPC-6012 TYPE 3 CLASS 2" at 12433.48,4400.64 h60
  text "OTHER +/-" at 12433.46,4244.64 h60
  text "BOW & TWIST:" at 11407.23,4087.64 h60
  text "X" at 12246.53,4087.64 h60
  text "ANSI IPC-6012 TYPE 3 CLASS 2" at 12433.48,4087.64 h60
  text "OTHER +/-" at 12433.46,3929.13 h60
  text "DRILLING:" at 11332.46,3790.64 h60
  text "REFERENCE:" at 11407.23,3673.64 h60
  text "X" at 12055.46,3673.64 h60
  text "AS SHOWN" at 12242.46,3673.64 h60
  text "X" at 12956.46,3673.64 h60
  text "NC_DRILL FILES" at 13093.46,3673.64 h60
  text "PTH MIN COPPER THICKNESS:" at 11407.23,3515.64 h60
  text "X" at 12757.46,3515.64 h60
  text "1MIL" at 12894.46,3515.64 h60
  text "OTHER" at 13391.46,3515.64 h60
  text "BOARD FINISH:" at 11332.46,3356.64 h60
  text "SILKSCREEN:" at 11487.68,3238.64 h60
  text "X" at 12436.46,3238.64 h60
  text "TOP" at 12562.46,3238.64 h60
  text "X" at 12946.46,3238.64 h60
  text "BOTTOM" at 13073.46,3238.64 h60
  text "SILKSCREEN COLOR:" at 11487.68,3071.64 h60
  text "X" at 12435.42,3071.64 h60
  text "WHITE" at 12562.46,3071.64 h60
  text "OTHER" at 13073.46,3071.64 h60
  text "X" at 12566.42,2912.44 h60
  text "GREEN" at 12693.46,2912.44 h60
  text "OTHER" at 13311.46,2912.44 h60
  text "SOLDER RESIST COLOR:" at 11487.68,2901.64 h60
  text "X" at 12566.42,2742.44 h60
  text "MATTE" at 12693.46,2742.44 h60
  text "SEMI-GLOSS" at 13311,2741.8 h60
  text "IMMERSION GOLD (ENIG)" at 12393.46,2553.92 h60
  text "ENEPIG" at 13731,2550.64 h60
  text "SURFACE FINISH:" at 11332.46,2549.64 h60
  text "X" at 12206.51,2549.64 h60
  text "IMM. TIN/SILVER OR EQUIV" at 11662,2392.64 h60
  text "OTHER" at 13093.46,2392.64 h60
  text "ARRAY/PANEL:" at 11332.46,2213.64 h60
  text "CUT AND TRIM PER M1 BOARD OUTLINE" at 12393.46,2209.35 h60
  text "N.C. ROUTE" at 12393.46,2057.64 h60
  text "X" at 13072.46,2057.64 h60
  text "V. SCORE" at 13259.46,2057.64 h60
  text "CERTIFICATION:" at 11332.46,1920.64 h60
  text "MATERIALS AND WORKMANSHIP FOR ALL PCBS" at 12057.46,1920.64 h60
  text "TO MEET OR EXCEED THE REQUIREMENTS OF:" at 12057.46,1822.64 h60
  text "X" at 11683.96,1686.13 h60
  text "ANSI IPC-A-600F CLASS ->" at 11822.96,1686.13 h60
  text "X" at 13462.02,1686.13 h60
  text "2" at 13580.96,1686.14 h60
  text "1" at 13265.96,1684.64 h60
  text "3" at 13934.96,1684.64 h60
  text "X" at 11686.02,1526.64 h60
  text "UL 94V-0" at 11822.96,1526.64 h60
  text "X" at 12498.02,1526.64 h60
  text "RoHS" at 12634.96,1526.64 h60
  text "OTHER" at 13279.36,1526.64 h60
  text "PER ORDER" at 13676.42,1526.64 h60
  text "ADDITIONAL REQUIREMENTS:" at 11332.46,1385.64 h60
  text "MICROSECTION:" at 11407.23,1270.64 h60
  text "YES" at 12312.96,1270.64 h60
  text "REQUIRED" at 13174.46,1114.49 h60
  text "BARE BOARD ELEC. TEST:" at 11407.23,1111.64 h60
  text "NONE" at 12712.96,1111.64 h60
  text "X" at 13047.46,1111.64 h60
  text "PER ORDER" at 13766.46,1111.64 h60
  text "MANUFACTURER'S UL:" at 11407.23,954.64 h60
  text "RAIL" at 12572.96,950.35 h60
  text "METAL" at 13064.77,950.35 h60
  text "X" at 13440,950 h60
  text "SILK" at 13576.46,950.35 h60
  text ".Layer_Name" at 577,-858.49 h60
M11 Gerber Information:
  lines w10: -292,-930.17 6308,-930.17 ; -292,-726.83 6310,-726.83 ; -292,-523.5 -292,-1133.5 3713,-1133.5 6310,-1133.5 6310,-523.5 -291.5,-523.5 -291.5,-1133.5 1284,-1133.5 ; 2173,-1133.5 2173,-523.5 ; 3440,-726.83 3440,-523.5 ; 4280,-726.83 4280,-523.5 ; 4902,-1140 4902,-937.17
  text "ALL ARTWORK VIEWED FROM TOP SIDE" at -228.5,-655.67 h60
  text "BOARD #:" at 2248,-655.67 h60
  text ".PRJ_Number" at 2793.5,-655.67 h60
  text "REV:" at 3638,-655.67 h60
  text ".PCB_Rev" at 3929.5,-655.67 h60
  text "SVN REV:" at 4476,-655.67 h60
  text ".VersionControl_RevNumber" at 4982,-655.67 h60
  text "LAYER NAME =" at -228.5,-858.49 h60
  text "TID #:" at 2248,-859 h60
  text ".TID" at 2793.5,-859 h60
  text "PLOT NAME =" at -228.5,-1064.34 h60
  text ".plot_File_Name" at 577,-1064.34 h60
  text "GENERATED    :" at 2250,-1064.34 h60
  text ".Print_Date" at 3119.5,-1064.34 h60
  text ".Print_Time" at 3848.5,-1064.34 h60
  text "TEXAS INSTRUMENTS" at 5113,-1064.34 h60
M12 Stackup:
  drawing of 191 lines, arcs and shapes, not listed
  text "Layer" at 9790.58,7830 h60
  text "Name" at 10200.49,7830 h60
  text "Material" at 11130.23,7830 h60
  text "Thickness" at 11990,7830 h60
  text "Constant" at 12639.84,7830 h60
  text "Board Layer Stack" at 13209.7,7830 h60
  text "1" at 9790.58,7710 h60
  text "Top Overlay" at 10200.49,7710 h60
  text "2" at 9790.58,7590 h60
  text "Top Solder" at 10200.49,7590 h60
  text "Solder Resist" at 11130.23,7590 h60
  text "0.40mil" at 11990,7590 h60
  text "3.5" at 12639.84,7590 h60
  text "3" at 9790.58,7470 h60
  text "Top Layer" at 10200.49,7470 h60
  text "Copper" at 11130.23,7470 h60
  text "1.40mil" at 11990,7470 h60
  text "4" at 9790.58,7350 h60
  text "Dielectric1" at 10200.49,7350 h60
  text "FR-4" at 11130.23,7350 h60
  text "59.20mil" at 11990,7350 h60
  text "4.8" at 12639.84,7350 h60
  text "5" at 9790.58,7230 h60
  text "Bottom Layer" at 10200.49,7230 h60
  text "Copper" at 11130.23,7230 h60
  text "1.40mil" at 11990,7230 h60
  text "6" at 9790.58,7110 h60
  text "Bottom Solder" at 10200.49,7110 h60
  text "Solder Resist" at 11130.23,7110 h60
  text "0.40mil" at 11990,7110 h60
  text "3.5" at 12639.84,7110 h60
  text "7" at 9790.58,6990 h60
  text "Bottom Overlay" at 10200.49,6990 h60
  text ".Layer_Name" at 577,-858.49 h60
M13 Component Bodies Top:
  text ".Layer_Name" at 577,-858.49 h60
M14 Component Bodies Bottom:
  text ".Layer_Name" at 577,-858.49 h60
M15 Courtyards Top:
  text ".Layer_Name" at 577,-858.49 h60
M16 Courtyards Bottom:
  text ".Layer_Name" at 577,-858.49 h60
Drill Drawing:
  lines w10: 5536.09,2000.78 5536.09,2014.59 5549.9,2028.4 5536.09,2042.22 5536.09,2056.03 5549.9,2056.03 5563.72,2042.22 5577.53,2056.03 5591.34,2056.03 5591.34,2042.22 5577.53,2028.4 5591.34,2014.59 5591.34,2000.78 5577.53,2000.78 5563.72,2014.59 5549.9,2000.78 5536.09,2000.78 ; 5536.09,2511.87 5549.9,2511.87 5563.72,2498.06 5577.53,2511.87 5591.34,2511.87 5577.53,2525.68 5591.34,2539.5 5577.53,2539.5 5563.72,2553.31 5549.9,2539.5 5536.09,2539.5 5549.9,2525.68 5536.09,2511.87 ; 5536.09,2801.95 5591.34,2801.95 5563.72,2746.7 5536.09,2801.95 ; 5536.09,2871.02 5563.72,2884.83 5591.34,2871.02 5577.53,2898.64 5591.34,2926.27 5563.72,2912.46 5536.09,2926.27 5549.9,2898.64 5536.09,2871.02 ; 5547.14,2011.83 5547.14,2020.12 5555.43,2028.4 5547.14,2036.69 5547.14,2044.98 5555.43,2044.98 5563.72,2036.69 5572.01,2044.98 5580.29,2044.98 5580.29,2036.69 5572.01,2028.4 5580.29,2020.12 5580.29,2011.83 5572.01,2011.83 5563.72,2020.12 5555.43,2011.83 5547.14,2011.83 ; 5547.14,2517.4 5555.43,2517.4 5563.72,2509.11 5572.01,2517.4 5580.29,2517.4 5572.01,2525.68 5580.29,2533.97 5572.01,2533.97 5563.72,2542.26 5555.43,2533.97 5547.14,2533.97 5555.43,2525.68 5547.14,2517.4 ; 5547.14,2790.9 5580.29,2790.9 5563.72,2757.75 5547.14,2790.9 ; 5547.14,2882.07 5563.72,2890.36 5580.29,2882.07 5572.01,2898.64 5580.29,2915.22 5563.72,2906.93 5547.14,2915.22 5555.43,2898.64 5547.14,2882.07
  lines w12: 5486,1963.48 7464.02,1963.48 ; 5486,3331 7464.02,3331 ; 5823.86,1839.16 5823.86,3455.32 ; 6155.86,1839.16 6155.86,3455.32 ; 6792.43,1839.16 6792.43,3455.32 ; 7051.57,1839.16 7051.57,3455.32 ; 5486,1839.16 7464.02,1839.16 7464.02,3455.32 5486,3455.32 5486,1839.16
  text "Symbol" at 5560.59,3368.3 h72
  text "Quantity" at 5861.16,3368.3 h72
  text "Finished Hole Size" at 6193.16,3368.3 h72
  text "Plated" at 6829.72,3368.3 h72
  text "Hole Type" at 7088.86,3368.3 h72
  text "2" at 5861.16,3243.98 h60
  text "118.11mil (3.000mm)" at 6193.16,3243.98 h60
  text "NPTH" at 6829.72,3243.98 h60
  text "Round" at 7088.86,3243.98 h60
  text "A" at 5535.31,3233.99 h55.25
  text "55" at 5861.16,3119.66 h60
  text "12.00mil (0.305mm)" at 6193.16,3119.66 h60
  text "PTH" at 6829.72,3119.66 h60
  text "Round" at 7088.86,3119.66 h60
  text "D" at 5535.31,3109.67 h55.25
  text "2" at 5861.16,2995.34 h60
  text "29.53mil (0.750mm)" at 6193.16,2995.34 h60
  text "PTH" at 6829.72,2995.34 h60
  text "Round" at 7088.86,2995.34 h60
  text "C" at 5535.31,2985.35 h55.25
  text "6" at 5861.16,2871.02 h60
  text "33.46mil (0.850mm)" at 6193.16,2871.02 h60
  text "PTH" at 6829.72,2871.02 h60
  text "Round" at 7088.86,2871.02 h60
  text "2" at 5861.16,2746.7 h60
  text "35.00mil (0.889mm)" at 6193.16,2746.7 h60
  text "PTH" at 6829.72,2746.7 h60
  text "Round" at 7088.86,2746.7 h60
  text "6" at 5861.16,2622.38 h60
  text "40.00mil (1.016mm)" at 6193.16,2622.38 h60
  text "PTH" at 6829.72,2622.38 h60
  text "Round" at 7088.86,2622.38 h60
  text "B" at 5535.31,2612.39 h55.25
  text "6" at 5861.16,2498.06 h60
  text "43.31mil (1.100mm)" at 6193.16,2498.06 h60
  text "PTH" at 6829.72,2498.06 h60
  text "Round" at 7088.86,2498.06 h60
  text "2" at 5861.16,2373.74 h60
  text "55.12mil (1.400mm)" at 6193.16,2373.74 h60
  text "PTH" at 6829.72,2373.74 h60
  text "Round" at 7088.86,2373.74 h60
  text "G" at 5535.31,2363.75 h55.25
  text "10" at 5861.16,2249.42 h60
  text "57.09mil (1.450mm)" at 6193.16,2249.42 h60
  text "PTH" at 6829.72,2249.42 h60
  text "Round" at 7088.86,2249.42 h60
  text "F" at 5535.31,2239.43 h55.25
  text "2" at 5861.16,2125.1 h60
  text "39.37mil (1.000mm)" at 6193.16,2125.1 h60
  text "PTH" at 6829.72,2125.1 h60
  text "Slot" at 7088.86,2125.1 h60
  text "E" at 5535.31,2115.11 h55.25
  text "2" at 5861.16,2000.78 h60
  text "47.24mil (1.200mm)" at 6193.16,2000.78 h60
  text "PTH" at 6829.72,2000.78 h60
  text "Slot" at 7088.86,2000.78 h60
  text "95 Total" at 5861.16,1876.46 h60
  text "Slot definitions :" at 5560.59,1789.43 h60
  text "Routed Path Length" at 6011.31,1789.43 h60
  text "= Calculated from tool start centre position to tool end centre position." at 6551.05,1789.43 h60
  text "Hole Length" at 6011.31,1739.71 h60
  text "= Routed Path Length + Tool Size = Slot length as defined in the PCB layout" at 6351.24,1739.71 h60
  text ".Layer_Name" at 577,-858.49 h60

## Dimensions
0,0 to 3400,0 on M2 Board Dimensions
0,-400 to 1000,-400 on M2 Board Dimensions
